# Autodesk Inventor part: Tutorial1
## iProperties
Created: 2005-02
Part Number: Tutorial1
Document SubType Name: Modeling
Designer: CADCIM
Manufacturer: Standard
Standards Organization: Custom
Author: CADCIM
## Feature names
1. Extrusion1
2. Extrusion2
3. Extrusion3
